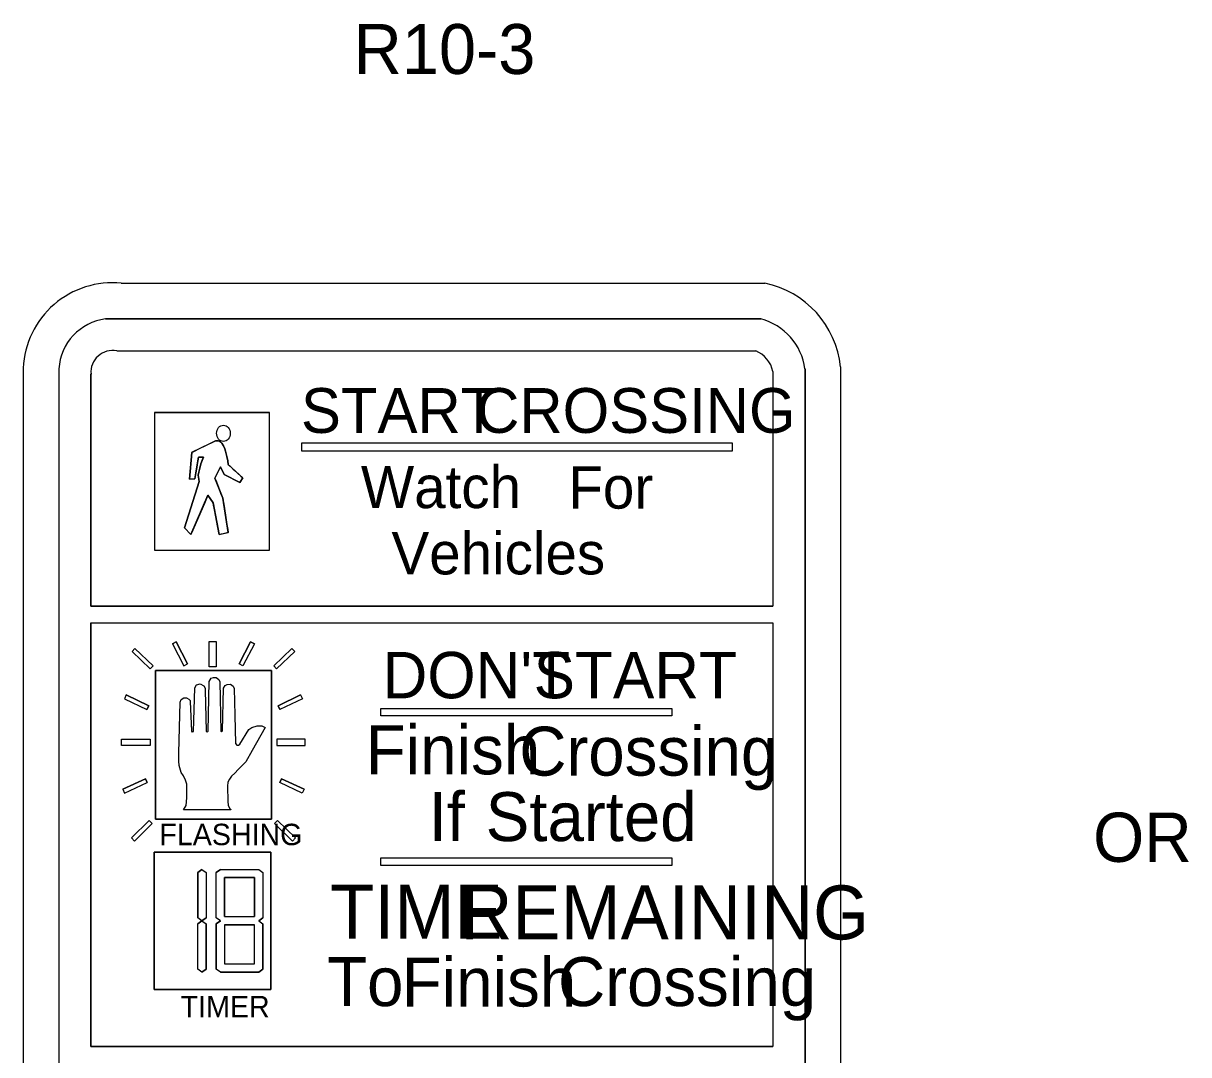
# Model space of a CAD drawing. Extents: x 1896459 to 1901611, y 1616229 to 1617416.
# Drawn here: x 1897736.4 to 1897899.9, y 1616970 to 1617114.6 of the extents above; entities that cross this region are included whole.
import ezdxf

# ---------------------------------------------------------------- set-up
doc = ezdxf.new("R2010")
doc.units = 0
for name, color, linetype in [('Level 8', 7, 'Continuous'), ('ROW_PR_Notes', 7, 'Continuous'), ('Signals_EX_Above Ground', 7, 'Continuous')]:
    doc.layers.add(name, color=color, linetype=linetype)

msp = doc.modelspace()

# ---------------------------------------------------------------- linework, layer by layer
at = {"layer": 'ROW_PR_Notes'}
for p, q in [((1897750.14, 1617078.14), (1897840.44, 1617078.14)), ((1897747.95, 1617073.14), (1897839.86, 1617073.14)), ((1897839.86, 1617073.14), (1897747.95, 1617073.14)), ((1897749.51, 1617068.64), (1897839.17, 1617068.64)), ((1897749.51, 1617068.64), (1897839.17, 1617068.64)), ((1897736.4, 1617066.24), (1897736.4, 1616898.74)), ((1897741.4, 1617066.11), (1897741.4, 1616899.07)), ((1897741.4, 1617066.11), (1897741.4, 1616899.07)), ((1897745.9, 1617065.41), (1897745.9, 1617032.87)), ((1897745.9, 1617032.87), (1897745.9, 1617065.41)), ((1897841.57, 1617065.75), (1897841.57, 1617032.87)), ((1897841.57, 1617065.75), (1897841.57, 1617032.87)), ((1897846.07, 1617066.11), (1897846.07, 1616899.07)), ((1897846.07, 1616899.07), (1897846.07, 1617066.11)), ((1897851.07, 1617066.41), (1897851.07, 1616898.82)), ((1897754.8, 1617060.03), (1897770.96, 1617060.03)), ((1897770.96, 1617060.03), (1897754.8, 1617060.03)), ((1897762.97, 1617055.86), (1897763.37, 1617056.04)), ((1897759.73, 1617050.65), (1897760.04, 1617054.42)), ((1897764.86, 1617054.21), (1897764.95, 1617053.85)), ((1897764.95, 1617053.85), (1897765.09, 1617053.23)), ((1897761.01, 1617051.65), (1897761.15, 1617052.22)), ((1897764.56, 1617051.34), (1897764.07, 1617052.39)), ((1897765.09, 1617053.23), (1897765.15, 1617052.74)), ((1897760.47, 1617050.73), (1897759.73, 1617050.65)), ((1897760.95, 1617051.24), (1897761.01, 1617051.65)), ((1897761.09, 1617050.34), (1897761.01, 1617050.62)), ((1897766.79, 1617050.19), (1897764.56, 1617051.34)), ((1897767.19, 1617050.84), (1897766.79, 1617050.19)), ((1897759.03, 1617043.83), (1897761.09, 1617050.34)), ((1897763.41, 1617045.39), (1897763.02, 1617047.33)), ((1897759.91, 1617042.89), (1897759.03, 1617043.83)), ((1897745.9, 1617032.87), (1897841.57, 1617032.87)), ((1897841.57, 1617032.87), (1897745.9, 1617032.87)), ((1897745.9, 1617030.54), (1897841.57, 1617030.54)), ((1897745.9, 1617030.54), (1897745.9, 1616971.14)), ((1897745.9, 1616971.14), (1897745.9, 1617030.54)), ((1897745.9, 1617030.54), (1897841.57, 1617030.54)), ((1897841.57, 1617030.54), (1897841.57, 1616971.14)), ((1897841.57, 1617030.54), (1897841.57, 1616971.14)), ((1897757.32, 1617027.6), (1897757.85, 1617027.87)), ((1897757.85, 1617027.87), (1897757.32, 1617027.6)), ((1897757.32, 1617027.6), (1897758.94, 1617024.49)), ((1897757.32, 1617027.6), (1897758.94, 1617024.49)), ((1897757.85, 1617027.87), (1897759.46, 1617024.77)), ((1897759.46, 1617024.77), (1897757.85, 1617027.87)), ((1897768.3, 1617027.87), (1897766.69, 1617024.77)), ((1897766.69, 1617024.77), (1897768.3, 1617027.87)), ((1897768.83, 1617027.6), (1897767.22, 1617024.49)), ((1897768.83, 1617027.6), (1897767.22, 1617024.49)), ((1897768.83, 1617027.6), (1897768.3, 1617027.87)), ((1897768.3, 1617027.87), (1897768.83, 1617027.6)), ((1897752.07, 1617026.91), (1897751.67, 1617026.48)), ((1897752.07, 1617026.91), (1897751.67, 1617026.48)), ((1897751.67, 1617026.48), (1897754.21, 1617024.07)), ((1897751.67, 1617026.48), (1897754.21, 1617024.07)), ((1897752.07, 1617026.91), (1897754.62, 1617024.5)), ((1897754.62, 1617024.5), (1897752.07, 1617026.91)), ((1897774.08, 1617026.91), (1897771.54, 1617024.5)), ((1897771.54, 1617024.5), (1897774.08, 1617026.91)), ((1897774.48, 1617026.48), (1897771.94, 1617024.07)), ((1897774.48, 1617026.48), (1897771.94, 1617024.07)), ((1897774.08, 1617026.91), (1897774.48, 1617026.48)), ((1897774.08, 1617026.91), (1897774.48, 1617026.48)), ((1897754.62, 1617024.5), (1897754.21, 1617024.07)), ((1897754.21, 1617024.07), (1897754.62, 1617024.5)), ((1897758.94, 1617024.49), (1897759.46, 1617024.77)), ((1897758.94, 1617024.49), (1897759.46, 1617024.77)), ((1897767.22, 1617024.49), (1897766.69, 1617024.77)), ((1897767.22, 1617024.49), (1897766.69, 1617024.77)), ((1897771.54, 1617024.5), (1897771.94, 1617024.07)), ((1897771.94, 1617024.07), (1897771.54, 1617024.5)), ((1897750.85, 1617020.41), (1897750.59, 1617019.88)), ((1897750.85, 1617020.41), (1897750.59, 1617019.88)), ((1897750.59, 1617019.88), (1897753.75, 1617018.37)), ((1897750.59, 1617019.88), (1897753.75, 1617018.37)), ((1897750.85, 1617020.41), (1897754.01, 1617018.9)), ((1897754.01, 1617018.9), (1897750.85, 1617020.41)), ((1897775.3, 1617020.41), (1897772.15, 1617018.9)), ((1897772.15, 1617018.9), (1897775.3, 1617020.41)), ((1897775.56, 1617019.88), (1897772.4, 1617018.37)), ((1897775.56, 1617019.88), (1897772.4, 1617018.37)), ((1897775.3, 1617020.41), (1897775.56, 1617019.88)), ((1897775.3, 1617020.41), (1897775.56, 1617019.88)), ((1897754.01, 1617018.9), (1897753.75, 1617018.37)), ((1897753.75, 1617018.37), (1897754.01, 1617018.9)), ((1897772.15, 1617018.9), (1897772.4, 1617018.37)), ((1897772.4, 1617018.37), (1897772.15, 1617018.9)), ((1897750.36, 1617007.19), (1897753.54, 1617008.66)), ((1897753.54, 1617008.66), (1897750.36, 1617007.19)), ((1897750.61, 1617006.66), (1897753.79, 1617008.13)), ((1897750.61, 1617006.66), (1897753.79, 1617008.13)), ((1897753.54, 1617008.66), (1897753.79, 1617008.13)), ((1897753.79, 1617008.13), (1897753.54, 1617008.66)), ((1897772.62, 1617008.66), (1897772.37, 1617008.13)), ((1897772.37, 1617008.13), (1897772.62, 1617008.66)), ((1897775.54, 1617006.66), (1897772.37, 1617008.13)), ((1897775.54, 1617006.66), (1897772.37, 1617008.13)), ((1897775.79, 1617007.19), (1897772.62, 1617008.66)), ((1897772.62, 1617008.66), (1897775.79, 1617007.19)), ((1897750.36, 1617007.19), (1897750.61, 1617006.66)), ((1897750.36, 1617007.19), (1897750.61, 1617006.66)), ((1897775.79, 1617007.19), (1897775.54, 1617006.66)), ((1897775.79, 1617007.19), (1897775.54, 1617006.66)), ((1897765.51, 1617004.32), (1897765.52, 1617004.33)), ((1897765.52, 1617004.33), (1897765.51, 1617004.32)), ((1897751.58, 1617000.36), (1897754.08, 1617002.8)), ((1897754.08, 1617002.8), (1897751.58, 1617000.36)), ((1897751.99, 1616999.93), (1897754.49, 1617002.38)), ((1897751.99, 1616999.93), (1897754.49, 1617002.38)), ((1897754.08, 1617002.8), (1897754.49, 1617002.38)), ((1897754.49, 1617002.38), (1897754.08, 1617002.8)), ((1897772.07, 1617002.8), (1897771.66, 1617002.38)), ((1897771.66, 1617002.38), (1897772.07, 1617002.8)), ((1897774.16, 1616999.93), (1897771.66, 1617002.38)), ((1897774.16, 1616999.93), (1897771.66, 1617002.38)), ((1897774.57, 1617000.36), (1897772.07, 1617002.8)), ((1897772.07, 1617002.8), (1897774.57, 1617000.36)), ((1897751.58, 1617000.36), (1897751.99, 1616999.93)), ((1897751.58, 1617000.36), (1897751.99, 1616999.93)), ((1897774.57, 1617000.36), (1897774.16, 1616999.93)), ((1897774.57, 1617000.36), (1897774.16, 1616999.93)), ((1897761.47, 1616995.96), (1897760.9, 1616995.54)), ((1897760.9, 1616995.54), (1897761.47, 1616995.96)), ((1897760.9, 1616995.54), (1897760.9, 1616989.18)), ((1897760.9, 1616989.18), (1897760.9, 1616995.54)), ((1897761.47, 1616995.96), (1897762.05, 1616995.54)), ((1897761.47, 1616995.96), (1897762.05, 1616995.54)), ((1897762.05, 1616995.54), (1897762.05, 1616989.18)), ((1897762.05, 1616995.54), (1897762.05, 1616989.18)), ((1897764.05, 1616995.96), (1897763.48, 1616995.54)), ((1897763.48, 1616995.54), (1897764.05, 1616995.96)), ((1897763.48, 1616989.18), (1897763.48, 1616995.54)), ((1897763.48, 1616989.18), (1897763.48, 1616995.54)), ((1897764.05, 1616995.96), (1897769.43, 1616995.96)), ((1897764.05, 1616995.96), (1897769.43, 1616995.96)), ((1897769.43, 1616995.96), (1897770, 1616995.54)), ((1897769.43, 1616995.96), (1897770, 1616995.54)), ((1897770, 1616995.54), (1897770, 1616989.18)), ((1897770, 1616995.54), (1897770, 1616989.18)), ((1897764.63, 1616994.81), (1897768.85, 1616994.81)), ((1897764.63, 1616989.34), (1897764.63, 1616994.81)), ((1897768.85, 1616994.81), (1897764.63, 1616994.81)), ((1897764.63, 1616994.81), (1897764.63, 1616989.34)), ((1897768.85, 1616994.81), (1897768.85, 1616989.34)), ((1897768.85, 1616989.34), (1897768.85, 1616994.81)), ((1897761.47, 1616988.76), (1897760.9, 1616989.18)), ((1897761.47, 1616988.76), (1897760.9, 1616989.18)), ((1897761.47, 1616988.76), (1897760.9, 1616988.33)), ((1897760.9, 1616988.33), (1897761.47, 1616988.76)), ((1897761.47, 1616988.76), (1897762.05, 1616989.18)), ((1897762.05, 1616989.18), (1897761.47, 1616988.76)), ((1897761.47, 1616988.76), (1897762.05, 1616988.33)), ((1897761.47, 1616988.76), (1897762.05, 1616988.33)), ((1897764.05, 1616988.76), (1897763.48, 1616989.18)), ((1897764.05, 1616988.76), (1897763.48, 1616989.18)), ((1897764.05, 1616988.76), (1897763.48, 1616988.33)), ((1897764.05, 1616988.76), (1897763.48, 1616988.33)), ((1897763.48, 1616988.33), (1897764.05, 1616988.76)), ((1897764.63, 1616989.34), (1897768.85, 1616989.34)), ((1897764.63, 1616989.34), (1897768.85, 1616989.34)), ((1897769.43, 1616988.76), (1897770, 1616989.18)), ((1897770, 1616989.18), (1897769.43, 1616988.76)), ((1897769.43, 1616988.76), (1897770, 1616988.33)), ((1897769.43, 1616988.76), (1897770, 1616988.33)), ((1897769.43, 1616988.76), (1897770, 1616988.33)), ((1897760.9, 1616981.98), (1897760.9, 1616988.33)), ((1897760.9, 1616981.98), (1897760.9, 1616988.33)), ((1897762.05, 1616981.98), (1897762.05, 1616988.33)), ((1897762.05, 1616988.33), (1897762.05, 1616981.98)), ((1897763.48, 1616988.33), (1897763.48, 1616981.98)), ((1897763.48, 1616981.98), (1897763.48, 1616988.33)), ((1897764.63, 1616988.17), (1897764.63, 1616982.7)), ((1897764.63, 1616988.17), (1897768.85, 1616988.17)), ((1897764.63, 1616988.17), (1897764.63, 1616982.7)), ((1897768.85, 1616988.17), (1897764.63, 1616988.17)), ((1897768.85, 1616982.7), (1897768.85, 1616988.17)), ((1897768.85, 1616982.7), (1897768.85, 1616988.17)), ((1897770, 1616981.98), (1897770, 1616988.33)), ((1897770, 1616988.33), (1897770, 1616981.98)), ((1897761.47, 1616981.55), (1897760.9, 1616981.98)), ((1897761.47, 1616981.55), (1897760.9, 1616981.98)), ((1897761.47, 1616981.55), (1897762.05, 1616981.98)), ((1897762.05, 1616981.98), (1897761.47, 1616981.55)), ((1897764.05, 1616981.55), (1897763.48, 1616981.98)), ((1897764.05, 1616981.55), (1897763.48, 1616981.98)), ((1897764.63, 1616982.7), (1897768.85, 1616982.7)), ((1897764.63, 1616982.7), (1897768.85, 1616982.7)), ((1897769.43, 1616981.55), (1897770, 1616981.98)), ((1897770, 1616981.98), (1897769.43, 1616981.55)), ((1897764.05, 1616981.55), (1897769.43, 1616981.55)), ((1897769.43, 1616981.55), (1897764.05, 1616981.55)), ((1897745.9, 1616971.14), (1897841.57, 1616971.14)), ((1897841.57, 1616971.14), (1897745.9, 1616971.14))]:
    msp.add_line(p, q, dxfattribs=at)
for points in [[(1897754.8, 1617060.03), (1897754.8, 1617040.71), (1897770.96, 1617040.71), (1897770.96, 1617060.03)], [(1897754.8, 1617060.03), (1897754.8, 1617040.71), (1897770.96, 1617040.71), (1897770.96, 1617060.03)], [(1897760.04, 1617054.42), (1897761.39, 1617055.09), (1897762.97, 1617055.86)], [(1897763.37, 1617056.04), (1897763.74, 1617056.04), (1897763.94, 1617055.98)], [(1897763.94, 1617055.98), (1897764.13, 1617055.86), (1897764.27, 1617055.7), (1897764.5, 1617055.32), (1897764.67, 1617054.93), (1897764.77, 1617054.59), (1897764.86, 1617054.21)], [(1897761.15, 1617052.22), (1897761.33, 1617052.82), (1897761.55, 1617053.4), (1897761.68, 1617053.75), (1897760.98, 1617053.74), (1897760.81, 1617052.74), (1897760.73, 1617052.3)], [(1897760.73, 1617052.3), (1897760.61, 1617051.54), (1897760.47, 1617050.73)], [(1897764.07, 1617052.39), (1897763.7, 1617051.63), (1897763.29, 1617050.8), (1897763.5, 1617050.28), (1897763.93, 1617049.17), (1897764.39, 1617047.98)], [(1897765.15, 1617052.74), (1897765.82, 1617052.12), (1897767.19, 1617050.84)], [(1897761.01, 1617050.62), (1897760.96, 1617051.01), (1897760.95, 1617051.24)], [(1897763.02, 1617047.33), (1897762.31, 1617048.4), (1897761.81, 1617047.25), (1897760.02, 1617043.11), (1897759.91, 1617042.89)], [(1897764.51, 1617047.22), (1897764.52, 1617047.17), (1897764.62, 1617046.54), (1897764.82, 1617045.27), (1897764.97, 1617044.3), (1897765.08, 1617043.61), (1897765.14, 1617043.19), (1897764.42, 1617043), (1897763.9, 1617042.89), (1897763.7, 1617043.89), (1897763.5, 1617044.87), (1897763.41, 1617045.39)], [(1897764.39, 1617047.98), (1897764.41, 1617047.88), (1897764.42, 1617047.8)], [(1897764.42, 1617047.8), (1897764.45, 1617047.62), (1897764.51, 1617047.22)], [(1897754.95, 1617003), (1897771.2, 1617003), (1897771.2, 1617023.84), (1897754.95, 1617023.84), (1897754.95, 1617003)], [(1897765.51, 1617004.32), (1897758.89, 1617004.32), (1897759.23, 1617004.89), (1897759.35, 1617006), (1897759.36, 1617007.12), (1897759.34, 1617007.88), (1897759.18, 1617008.48), (1897758.86, 1617009.06), (1897758.55, 1617009.55), (1897758.28, 1617010.52), (1897758.22, 1617011.14), (1897758.23, 1617012.26), (1897758.39, 1617019.39), (1897758.55, 1617019.79), (1897758.93, 1617019.99), (1897759.28, 1617020.01), (1897759.62, 1617019.82), (1897759.79, 1617019.61), (1897759.81, 1617019.5), (1897760.02, 1617015.31), (1897760.09, 1617015.21), (1897760.15, 1617015.24), (1897760.27, 1617015.29), (1897760.45, 1617021.41), (1897760.71, 1617021.81), (1897761.22, 1617021.96), (1897761.74, 1617021.69), (1897761.92, 1617021.36), (1897761.94, 1617021.07), (1897762.07, 1617015.35), (1897762.18, 1617015.23), (1897762.32, 1617015.33), (1897762.48, 1617022.3), (1897762.78, 1617022.75), (1897763.08, 1617022.88), (1897763.47, 1617022.84), (1897763.82, 1617022.58), (1897763.96, 1617022.26), (1897764.1, 1617015.33), (1897764.23, 1617015.24), (1897764.35, 1617015.36), (1897764.49, 1617021.37), (1897764.71, 1617021.73), (1897765.01, 1617021.89), (1897765.48, 1617021.91), (1897765.83, 1617021.64), (1897765.98, 1617021.32), (1897766.06, 1617017.56), (1897766.17, 1617013.6), (1897766.34, 1617013.39), (1897766.59, 1617013.37), (1897766.78, 1617013.52), (1897768.04, 1617015.55), (1897768.47, 1617015.87), (1897769.23, 1617016.09), (1897769.89, 1617016.07), (1897770.34, 1617015.87), (1897768.51, 1617012.62), (1897767.61, 1617011.04), (1897767.36, 1617010.76), (1897767.05, 1617010.45), (1897766.57, 1617009.98), (1897766.06, 1617009.43), (1897765.63, 1617009.03), (1897765.31, 1617008.62), (1897765.12, 1617008.19), (1897765.07, 1617007.64), (1897765.08, 1617005.45), (1897765.16, 1617004.96), (1897765.35, 1617004.54), (1897765.52, 1617004.33)], [(1897754.74, 1616979.12), (1897771.12, 1616979.12), (1897771.12, 1616998.36), (1897754.74, 1616998.36), (1897754.74, 1616979.12)]]:
    msp.add_lwpolyline(points, dxfattribs=at)
for points in [[(1897759.73, 1617050.65), (1897760.47, 1617050.73), (1897760.98, 1617053.74), (1897761.68, 1617053.75), (1897761.33, 1617052.82), (1897761.15, 1617052.22), (1897761.01, 1617051.65), (1897760.95, 1617051.24), (1897761.01, 1617050.62), (1897761.09, 1617050.34), (1897759.03, 1617043.83), (1897759.91, 1617042.89), (1897762.31, 1617048.4), (1897763.02, 1617047.33), (1897763.9, 1617042.89), (1897765.14, 1617043.19), (1897764.39, 1617047.98), (1897763.29, 1617050.8), (1897764.07, 1617052.39), (1897764.56, 1617051.34), (1897766.79, 1617050.19), (1897767.19, 1617050.84), (1897765.15, 1617052.74), (1897765.09, 1617053.23), (1897764.95, 1617053.85), (1897764.86, 1617054.21), (1897764.77, 1617054.59), (1897764.67, 1617054.93), (1897764.5, 1617055.32), (1897764.27, 1617055.7), (1897764.13, 1617055.86), (1897763.94, 1617055.98), (1897763.74, 1617056.04), (1897763.37, 1617056.04), (1897762.97, 1617055.86), (1897760.04, 1617054.42)], [(1897775.47, 1617055.75), (1897835.84, 1617055.75), (1897835.84, 1617054.61), (1897775.47, 1617054.61)], [(1897762.48, 1617027.92), (1897763.48, 1617027.92), (1897763.48, 1617024.36), (1897762.48, 1617024.36)], [(1897754.95, 1617023.84), (1897771.2, 1617023.84), (1897771.2, 1617003), (1897754.95, 1617003)], [(1897786.57, 1617018.52), (1897827.38, 1617018.52), (1897827.38, 1617017.46), (1897786.57, 1617017.46)], [(1897750.2, 1617014.23), (1897754.19, 1617014.23), (1897754.19, 1617013.31), (1897750.2, 1617013.31)], [(1897775.95, 1617014.23), (1897771.96, 1617014.23), (1897771.96, 1617013.31), (1897775.95, 1617013.31)], [(1897754.74, 1616998.36), (1897771.12, 1616998.36), (1897771.12, 1616979.12), (1897754.74, 1616979.12)], [(1897786.57, 1616997.57), (1897827.38, 1616997.57), (1897827.38, 1616996.51), (1897786.57, 1616996.51)]]:
    msp.add_lwpolyline(points, close=True, dxfattribs=at)
for centre, radius, start, end in [((1897748.91, 1617065.68), 12.52, 84.3429, 177.452), ((1897837.71, 1617064.99), 13.43, 6.0706, 78.2882), ((1897748.91, 1617065.68), 7.52, 97.3019, 176.7119), ((1897748.91, 1617065.68), 7.52, 97.3019, 176.7119), ((1897837.71, 1617064.99), 8.43, 7.6645, 75.2019), ((1897837.71, 1617064.99), 8.43, 7.6645, 75.2019), ((1897748.91, 1617065.68), 3.02, 78.4646, 185.1904), ((1897748.91, 1617065.68), 3.02, 78.4646, 185.1904), ((1897837.71, 1617064.99), 3.93, 11.2346, 68.2576), ((1897837.71, 1617064.99), 3.93, 11.2346, 68.2576)]:
    msp.add_arc(centre, radius, start, end, dxfattribs=at)
msp.add_ellipse((1897764.48, 1617057.09), major_axis=(0, -1.14), ratio=0.8364, dxfattribs=at)
at = {"layer": 'Signals_EX_Above Ground'}
for points in [[(1897760.04, 1617054.43), (1897762.57, 1617055.66), (1897762.97, 1617055.86), (1897763.37, 1617056.04), (1897763.74, 1617056.04), (1897763.94, 1617055.98), (1897764.13, 1617055.86), (1897764.27, 1617055.7), (1897764.5, 1617055.32), (1897764.67, 1617054.93), (1897764.77, 1617054.59), (1897764.86, 1617054.21), (1897764.95, 1617053.85), (1897765.09, 1617053.23), (1897765.15, 1617052.74), (1897765.38, 1617052.51), (1897765.82, 1617052.12), (1897766.18, 1617051.77), (1897766.52, 1617051.45), (1897766.92, 1617051.09), (1897767.19, 1617050.84), (1897766.79, 1617050.19), (1897764.56, 1617051.34), (1897764.07, 1617052.39), (1897763.7, 1617051.63), (1897763.29, 1617050.8), (1897763.49, 1617050.27), (1897763.71, 1617049.7), (1897763.93, 1617049.17), (1897764.09, 1617048.72), (1897764.22, 1617048.39), (1897764.39, 1617047.98), (1897764.41, 1617047.88), (1897764.44, 1617047.62), (1897764.52, 1617047.17), (1897764.62, 1617046.54), (1897764.82, 1617045.27), (1897764.97, 1617044.3), (1897765.08, 1617043.61), (1897765.14, 1617043.19), (1897764.42, 1617043), (1897763.9, 1617042.89), (1897763.7, 1617043.89), (1897763.5, 1617044.87), (1897763.26, 1617046.18), (1897763.09, 1617047.01), (1897763.02, 1617047.33), (1897762.31, 1617048.4), (1897761.81, 1617047.25), (1897760.02, 1617043.11), (1897759.91, 1617042.89), (1897759.03, 1617043.83), (1897761.09, 1617050.34), (1897761.01, 1617050.62), (1897760.96, 1617051.01), (1897760.95, 1617051.24), (1897761.01, 1617051.65), (1897761.15, 1617052.22), (1897761.33, 1617052.82), (1897761.55, 1617053.4), (1897761.68, 1617053.75), (1897760.98, 1617053.74), (1897760.81, 1617052.74), (1897760.61, 1617051.54), (1897760.47, 1617050.73), (1897759.73, 1617050.65), (1897760.04, 1617054.42)], [(1897765.51, 1617004.32), (1897758.89, 1617004.32), (1897759.23, 1617004.89), (1897759.35, 1617006), (1897759.36, 1617007.12), (1897759.34, 1617007.88), (1897759.18, 1617008.48), (1897758.86, 1617009.06), (1897758.55, 1617009.55), (1897758.28, 1617010.52), (1897758.22, 1617011.14), (1897758.23, 1617012.26), (1897758.39, 1617019.39), (1897758.55, 1617019.79), (1897758.93, 1617019.99), (1897759.28, 1617020.01), (1897759.62, 1617019.82), (1897759.79, 1617019.61), (1897759.81, 1617019.5), (1897760.02, 1617015.31), (1897760.09, 1617015.21), (1897760.15, 1617015.24), (1897760.27, 1617015.29), (1897760.45, 1617021.41), (1897760.71, 1617021.81), (1897761.22, 1617021.96), (1897761.74, 1617021.69), (1897761.92, 1617021.36), (1897761.94, 1617021.07), (1897762.07, 1617015.35), (1897762.18, 1617015.23), (1897762.32, 1617015.33), (1897762.48, 1617022.3), (1897762.78, 1617022.75), (1897763.08, 1617022.88), (1897763.47, 1617022.84), (1897763.82, 1617022.58), (1897763.96, 1617022.26), (1897764.1, 1617015.33), (1897764.23, 1617015.24), (1897764.35, 1617015.36), (1897764.49, 1617021.37), (1897764.71, 1617021.73), (1897765.01, 1617021.89), (1897765.48, 1617021.91), (1897765.83, 1617021.64), (1897765.98, 1617021.32), (1897766.06, 1617017.56), (1897766.17, 1617013.6), (1897766.34, 1617013.39), (1897766.59, 1617013.37), (1897766.78, 1617013.52), (1897768.04, 1617015.55), (1897768.47, 1617015.87), (1897769.23, 1617016.09), (1897769.89, 1617016.07), (1897770.34, 1617015.87), (1897768.51, 1617012.62), (1897767.61, 1617011.04), (1897767.36, 1617010.76), (1897767.05, 1617010.45), (1897766.57, 1617009.98), (1897766.06, 1617009.43), (1897765.63, 1617009.03), (1897765.31, 1617008.62), (1897765.12, 1617008.19), (1897765.07, 1617007.64), (1897765.08, 1617005.45), (1897765.16, 1617004.96), (1897765.35, 1617004.54), (1897765.52, 1617004.33)]]:
    msp.add_lwpolyline(points, dxfattribs=at)
msp.add_ellipse((1897764.48, 1617057.09), major_axis=(0, -1.14), ratio=0.8364, dxfattribs=at)

# ---------------------------------------------------------------- texts
at = {"layer": 'Level 8'}
for s, height, p in [('R10-3', 7, (1897782.75, 1617107.47)), ('OR', 6.901, (1897886.49, 1616997.01))]:
    msp.add_text(s, height=height, dxfattribs=at).set_placement(p)
at = {"layer": 'ROW_PR_Notes'}
for s, height, p in [('START', 6.284, (1897775.36, 1617057.15)), ('CROSSING', 6.284, (1897799.93, 1617057.15)), ('Watch', 5.929, (1897783.76, 1617046.6)), ('For', 5.929, (1897812.87, 1617046.53)), ('Vehicles', 5.929, (1897788.06, 1617037.31)), ("DON'T", 6.509, (1897786.8, 1617019.94)), ('START', 6.509, (1897808, 1617019.94)), ('Finish', 6.863, (1897784.44, 1617009.28)), ('Crossing', 6.863, (1897805.98, 1617009.1)), ('If', 6.863, (1897793.28, 1616999.92)), ('Started', 6.863, (1897801.27, 1616999.92)), ('FLASHING', 3.001, (1897755.49, 1616999.35)), ('TIME', 7.569, (1897779.46, 1616986.26)), ('REMAINING', 7.569, (1897797.72, 1616986.13)), ('To', 6.863, (1897779.02, 1616976.79)), ('Finish', 6.863, (1897789.49, 1616976.73)), ('Crossing', 6.863, (1897811.42, 1616976.79)), ('TIMER', 3.001, (1897758.48, 1616975.22))]:
    msp.add_text(s, height=height, dxfattribs=at).set_placement(p)

doc.saveas('drawing.dxf')
